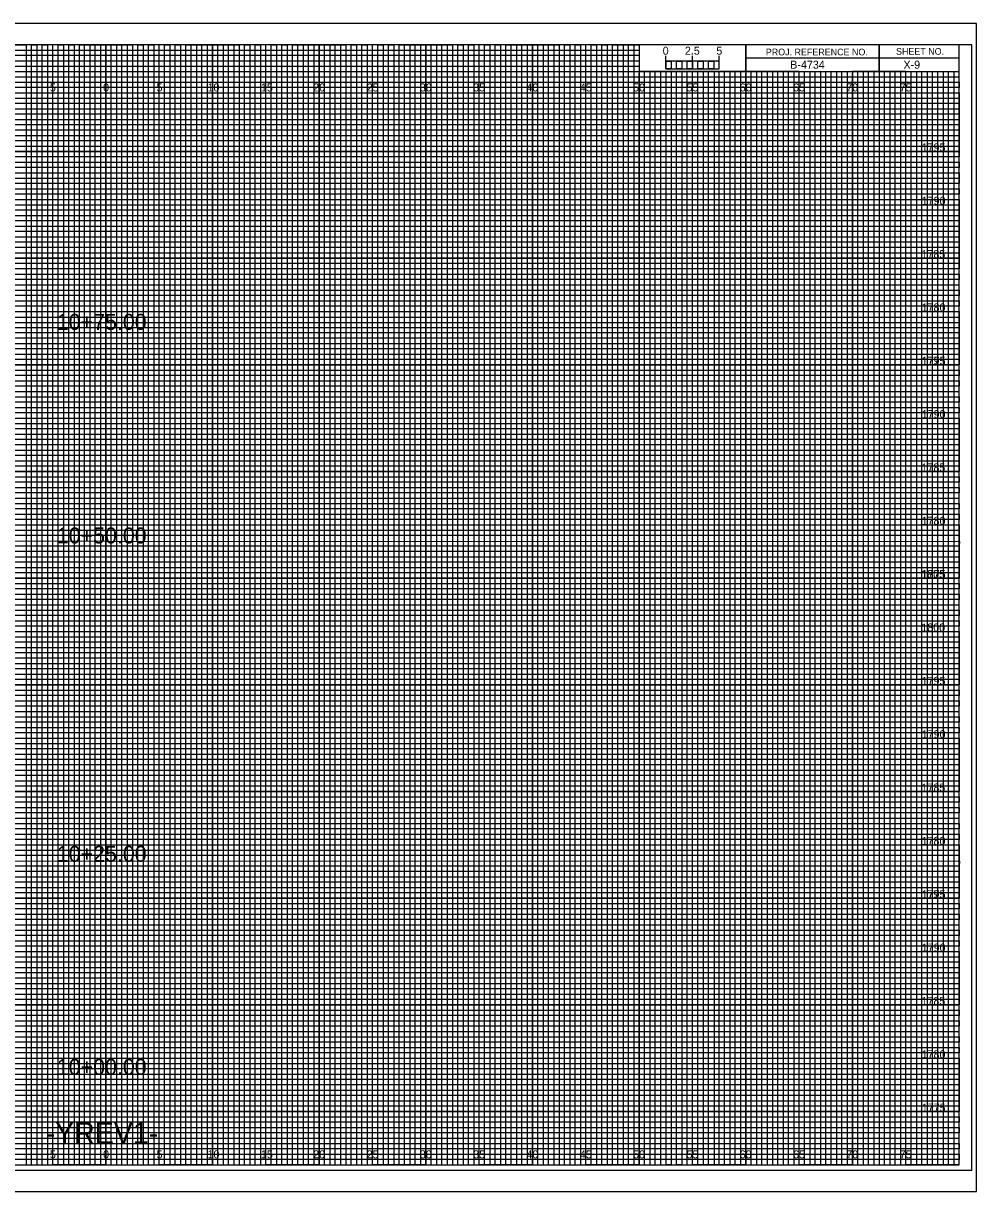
# Model space of a CAD drawing. Extents: x -7 to 162, y -2 to 107.
# Drawn here: x 72.2 to 161.7, y -2.5 to 107 of the extents above; entities that cross this region are included whole.
import ezdxf

# ---------------------------------------------------------------- set-up
doc = ezdxf.new("R2010")
doc.units = 0
for name, color, linetype in [('Exist Cross Section Cell', 7, 'Continuous'), ('Exist XS Center Line Elevation Label', 7, 'Continuous'), ('Exist XS Ground Line', 7, 'Continuous'), ('Prop XS Ditch Slope Text', 7, 'Continuous'), ('Prop XS Ditch Standard Text', 7, 'Continuous'), ('Prop XS Dump Level', 7, 'Continuous'), ('Prop XS Earthwork Shape', 7, 'Continuous'), ('Prop XS EOT Tick Mark', 7, 'Continuous'), ('Prop XS Finish Grade', 7, 'Continuous'), ('Prop XS Finish Grade Earthwork', 7, 'Continuous'), ('Prop XS Finish Grade Pavement', 7, 'Continuous'), ('Prop XS Pvmt Edge Slope', 7, 'Continuous'), ('Prop XS SE Text', 7, 'Continuous'), ('Prop XS Side Slope Text', 7, 'Continuous'), ('Prop XS SS Elevation Text', 7, 'Continuous'), ('Prop XS Subgrade Earthwork', 7, 'Continuous'), ('Scratch_Level_3', 7, 'Continuous')]:
    doc.layers.add(name, color=color, linetype=linetype)

msp = doc.modelspace()

# ---------------------------------------------------------------- linework, layer by layer
at = {"layer": 'Exist XS Center Line Elevation Label'}
for points in [[(67.5, 105), (72.5, 105), (72.5, 0), (77.5, 0), (77.5, 105), (82.5, 105), (82.5, 0), (87.5, 0), (87.5, 105), (92.5, 105), (92.5, 0), (97.5, 0), (97.5, 105), (102.5, 105), (102.5, 0), (107.5, 0), (107.5, 105), (112.5, 105), (112.5, 0), (117.5, 0), (117.5, 105), (122.5, 105), (122.5, 0), (127.5, 0), (127.5, 105), (129.97, 105), (130, 105), (130, 102.5), (132.5, 102.5), (132.5, 0), (137.5, 0), (137.5, 102.5), (142.5, 102.5), (142.5, 0), (147.5, 0), (147.5, 102.5), (152.5, 102.5), (152.5, 0), (157.5, 0), (157.5, 102.5)], [(0, 102.5), (137.5, 102.5)], [(0, 92.5), (160, 92.5), (160, 97.5), (0, 97.5)], [(0, 82.5), (160, 82.5), (160, 87.5), (0, 87.5)], [(0, 72.5), (160, 72.5), (160, 77.5), (0, 77.5)], [(0, 62.5), (160, 62.5), (160, 67.5), (0, 67.5)], [(0, 52.5), (160, 52.5), (160, 57.5), (0, 57.5)], [(0, 42.5), (160, 42.5), (160, 47.5), (0, 47.5)], [(0, 32.5), (160, 32.5), (160, 37.5), (0, 37.5)], [(0, 22.5), (160, 22.5), (160, 27.5), (0, 27.5)], [(0, 12.5), (160, 12.5), (160, 17.5), (0, 17.5)], [(0, 2.5), (160, 2.5), (160, 7.5), (0, 7.5)]]:
    msp.add_lwpolyline(points, dxfattribs=at)
at = {"layer": 'Exist XS Ground Line'}
for p, q in [((75, 105), (70, 105)), ((75, 0), (75, 105)), ((85, 105), (80, 105)), ((80, 105), (80, 0)), ((85, 0), (85, 105)), ((95, 105), (90, 105)), ((90, 105), (90, 0)), ((95, 0), (95, 105)), ((105, 105), (100, 105)), ((100, 105), (100, 0)), ((105, 0), (105, 105)), ((115, 105), (110, 105)), ((110, 105), (110, 0)), ((115, 0), (115, 105)), ((125, 105), (120, 105)), ((120, 105), (120, 0)), ((125, 0), (125, 105)), ((130, 105), (130, 0)), ((135, 0), (135, 102.5)), ((145, 102.5), (140, 102.5)), ((140, 102.5), (140, 0)), ((145, 0), (145, 102.5)), ((155, 102.5), (150, 102.5)), ((150, 102.5), (150, 0)), ((155, 0), (155, 102.5)), ((80, 0), (75, 0)), ((90, 0), (85, 0)), ((100, 0), (95, 0)), ((110, 0), (105, 0)), ((120, 0), (115, 0)), ((130, 0), (125, 0)), ((140, 0), (135, 0)), ((150, 0), (145, 0)), ((160, 0), (155, 0)), ((160, 0), (160, 0))]:
    msp.add_line(p, q, dxfattribs=at)
for points in [[(0, 100), (160, 100), (160, 95), (0, 95)], [(0, 90), (160, 90), (160, 85), (0, 85)], [(0, 80), (160, 80), (160, 75), (0, 75)], [(0, 70), (160, 70), (160, 65), (0, 65)], [(0, 60), (160, 60), (160, 55), (0, 55)], [(0, 50), (160, 50), (160, 45), (0, 45)], [(0, 40), (160, 40), (160, 35), (0, 35)], [(0, 30), (160, 30), (160, 25), (0, 25)], [(0, 20), (160, 20), (160, 15), (0, 15)], [(0, 10), (160, 10), (160, 5), (0, 5)]]:
    msp.add_lwpolyline(points, dxfattribs=at)
at = {"layer": 'Prop XS Ditch Slope Text'}
for p, q in [((132.5, 102.75), (132.5, 103.95)), ((132.5, 103.45), (132.5, 103.95)), ((135, 102.75), (135, 103.95)), ((137.5, 102.75), (137.5, 103.95)), ((137.5, 103.45), (137.5, 103.95))]:
    msp.add_line(p, q, dxfattribs=at)
for points in [[(137.5, 103.45), (132.5, 103.45), (132.5, 102.75), (137.5, 102.75)], [(132.5, 103.45), (133, 103.45), (133, 102.75), (132.5, 102.75)], [(133.5, 103.45), (134, 103.45), (134, 102.75), (133.5, 102.75)], [(134.5, 103.45), (135, 103.45), (135, 102.75), (134.5, 102.75)], [(135.5, 103.45), (136, 103.45), (136, 102.75), (135.5, 102.75)], [(136.5, 103.45), (137, 103.45), (137, 102.75), (136.5, 102.75)]]:
    msp.add_lwpolyline(points, close=True, dxfattribs=at)
at = {"layer": 'Prop XS Ditch Standard Text'}
for p, q in [((133.5, 102.5), (133, 102.5)), ((133, 102.5), (133, 0)), ((133.5, 0), (133.5, 102.5)), ((134.5, 102.5), (134, 102.5)), ((134, 102.5), (134, 0)), ((134.5, 0), (134.5, 102.5)), ((133, 0), (132.5, 0)), ((134, 0), (133.5, 0))]:
    msp.add_line(p, q, dxfattribs=at)
for points in [[(72.5, 0), (73, 0), (73, 105), (73.5, 105), (73.5, 0)], [(73.5, 0), (74, 0), (74, 105), (74.5, 105), (74.5, 0)], [(75, 0), (75.5, 0), (75.5, 105), (76, 105), (76, 0)], [(76, 0), (76.5, 0), (76.5, 105), (77, 105), (77, 0)], [(77.5, 0), (78, 0), (78, 105), (78.5, 105), (78.5, 0)], [(78.5, 0), (79, 0), (79, 105), (79.5, 105), (79.5, 0)], [(80, 0), (80.5, 0), (80.5, 105), (81, 105), (81, 0)], [(81, 0), (81.5, 0), (81.5, 105), (82, 105), (82, 0)], [(82.5, 0), (83, 0), (83, 105), (83.5, 105), (83.5, 0)], [(83.5, 0), (84, 0), (84, 105), (84.5, 105), (84.5, 0)], [(85, 0), (85.5, 0), (85.5, 105), (86, 105), (86, 0)], [(86, 0), (86.5, 0), (86.5, 105), (87, 105), (87, 0)], [(87.5, 0), (88, 0), (88, 105), (88.5, 105), (88.5, 0)], [(88.5, 0), (89, 0), (89, 105), (89.5, 105), (89.5, 0)], [(90, 0), (90.5, 0), (90.5, 105), (91, 105), (91, 0)], [(91, 0), (91.5, 0), (91.5, 105), (92, 105), (92, 0)], [(92.5, 0), (93, 0), (93, 105), (93.5, 105), (93.5, 0)], [(93.5, 0), (94, 0), (94, 105), (94.5, 105), (94.5, 0)], [(95, 0), (95.5, 0), (95.5, 105), (96, 105), (96, 0)], [(96, 0), (96.5, 0), (96.5, 105), (97, 105), (97, 0)], [(97.5, 0), (98, 0), (98, 105), (98.5, 105), (98.5, 0)], [(98.5, 0), (99, 0), (99, 105), (99.5, 105), (99.5, 0)], [(100, 0), (100.5, 0), (100.5, 105), (101, 105), (101, 0)], [(101, 0), (101.5, 0), (101.5, 105), (102, 105), (102, 0)], [(102.5, 0), (103, 0), (103, 105), (103.5, 105), (103.5, 0)], [(103.5, 0), (104, 0), (104, 105), (104.5, 105), (104.5, 0)], [(105, 0), (105.5, 0), (105.5, 105), (106, 105), (106, 0)], [(106, 0), (106.5, 0), (106.5, 105), (107, 105), (107, 0)], [(107.5, 0), (108, 0), (108, 105), (108.5, 105), (108.5, 0)], [(108.5, 0), (109, 0), (109, 105), (109.5, 105), (109.5, 0)], [(110, 0), (110.5, 0), (110.5, 105), (111, 105), (111, 0)], [(111, 0), (111.5, 0), (111.5, 105), (112, 105), (112, 0)], [(112.5, 0), (113, 0), (113, 105), (113.5, 105), (113.5, 0)], [(113.5, 0), (114, 0), (114, 105), (114.5, 105), (114.5, 0)], [(115, 0), (115.5, 0), (115.5, 105), (116, 105), (116, 0)], [(116, 0), (116.5, 0), (116.5, 105), (117, 105), (117, 0)], [(117.5, 0), (118, 0), (118, 105), (118.5, 105), (118.5, 0)], [(118.5, 0), (119, 0), (119, 105), (119.5, 105), (119.5, 0)], [(120, 0), (120.5, 0), (120.5, 105), (121, 105), (121, 0)], [(121, 0), (121.5, 0), (121.5, 105), (122, 105), (122, 0)], [(122.5, 0), (123, 0), (123, 105), (123.5, 105), (123.5, 0)], [(123.5, 0), (124, 0), (124, 105), (124.5, 105), (124.5, 0)], [(125, 0), (125.5, 0), (125.5, 105), (126, 105), (126, 0)], [(126, 0), (126.5, 0), (126.5, 105), (127, 105), (127, 0)], [(127.5, 0), (128, 0), (128, 105), (128.5, 105), (128.5, 0)], [(128.5, 0), (129, 0), (129, 105), (129.5, 105), (129.5, 0)], [(130, 0), (130.5, 0), (130.5, 102.5), (131.01, 102.5), (131.01, 0)], [(131, 0), (131.5, 0), (131.5, 102.5), (132, 102.5), (132, 0)], [(135, 0), (135.49, 0), (135.49, 102.5), (136, 102.5), (136, 0)], [(136, 0), (136.5, 0), (136.5, 102.5), (137.03, 102.5), (137.03, 0)], [(137.5, 0), (138, 0), (138, 102.5), (138.5, 102.5), (138.5, 0)], [(138.5, 0), (139, 0), (139, 102.5), (139.5, 102.5), (139.5, 0)], [(140, 0), (140.5, 0), (140.5, 102.5), (141, 102.5), (141, 0)], [(141, 0), (141.5, 0), (141.5, 102.5), (142, 102.5), (142, 0)], [(142.5, 0), (143, 0), (143, 102.5), (143.5, 102.5), (143.5, 0)], [(143.5, 0), (144, 0), (144, 102.5), (144.5, 102.5), (144.5, 0)], [(145, 0), (145.5, 0), (145.5, 102.5), (146, 102.5), (146, 0)], [(146, 0), (146.5, 0), (146.5, 102.5), (147, 102.5), (147, 0)], [(147.5, 0), (148, 0), (148, 102.5), (148.5, 102.5), (148.5, 0)], [(148.5, 0), (149, 0), (149, 102.5), (149.5, 102.5), (149.5, 0)], [(150, 0), (150.5, 0), (150.5, 102.5), (151, 102.5), (151, 0)], [(151, 0), (151.5, 0), (151.5, 102.5), (152, 102.5), (152, 0)], [(152.5, 0), (153, 0), (153, 102.5), (153.5, 102.5), (153.5, 0)], [(153.5, 0), (154, 0), (154, 102.5), (154.5, 102.5), (154.5, 0)], [(155, 0), (155.5, 0), (155.5, 102.5), (156, 102.5), (156, 0)], [(156, 0), (156.5, 0), (156.5, 102.5), (157, 102.5), (157, 0)], [(157.5, 0), (158, 0), (158, 102.5), (158.5, 102.5), (158.5, 0)], [(158.5, 0), (159, 0), (159, 102.5), (159.5, 102.5), (159.5, 0)]]:
    msp.add_lwpolyline(points, dxfattribs=at)
at = {"layer": 'Prop XS Dump Level'}
for p, q in [((0, 104.5), (130, 104.5)), ((130, 104.5), (130, 103.99)), ((130, 103.99), (0, 103.99)), ((0, 103.5), (130, 103.5)), ((130, 102.95), (0, 102.95)), ((130, 103.5), (130, 102.95)), ((0, 102), (160, 102))]:
    msp.add_line(p, q, dxfattribs=at)
for points in [[(0, 101.5), (135, 101.5), (160, 101.5), (160, 101), (0, 101)], [(0, 100.5), (160, 100.5), (160, 99.5), (0, 99.5)], [(0, 99), (160, 99), (160, 98.5), (0, 98.49)], [(0, 98), (160, 98), (160, 97), (0, 97)], [(0, 96.5), (160, 96.5), (160, 96), (0, 96)], [(0, 95.5), (160, 95.5), (160, 94.5), (0, 94.5)], [(0, 94), (160, 94), (160, 93.5), (0, 93.5)], [(0, 93), (160, 93), (160, 92), (0, 92)], [(0, 91.5), (160, 91.5), (160, 91), (0, 91)], [(0, 90.5), (160, 90.5), (160, 89.5), (0, 89.5)], [(0, 89), (160, 89), (160, 88.5), (0, 88.5)], [(0, 88), (160, 88), (160, 86.98), (160, 86.5), (160, 86), (0, 86)], [(0, 87), (160, 87), (160, 86.5), (0, 86.5)], [(0, 85.5), (160, 85.5), (160, 84.5), (0, 84.52)], [(0, 84.52), (160, 84.5), (160, 84), (0, 84)], [(0, 83.5), (160, 83.5), (160, 83), (0, 83)], [(0, 82), (160, 82), (160, 81.5), (0, 81.5)], [(0, 81), (160, 81), (160, 80.5), (0, 80.5)], [(-0.04, 79.45), (160, 79.45), (160, 78.94), (-0.04, 78.94)], [(0, 78.5), (160, 78.5), (160, 78), (0, 78)], [(0, 77), (160, 77), (160, 76.5), (0, 76.5)], [(0, 76), (160, 76), (160, 75.5), (0, 75.5)], [(0, 74.5), (160, 74.5), (160, 74), (0, 74)], [(0, 73.5), (160, 73.5), (160, 73), (0, 73)], [(0, 72), (160, 72), (160, 71.5), (0, 71.5)], [(0, 71), (160, 71), (160, 70.5), (0, 70.5)], [(0, 69.5), (160, 69.5), (160, 68.99), (0, 69)], [(0, 68.5), (160, 68.5), (160, 68), (0, 68)], [(0, 67), (160, 67), (160, 66.5), (0, 66.5)], [(0, 66), (160, 66), (160, 65.5), (0, 65.5)], [(0, 64.5), (160, 64.5), (160, 64), (0, 64)], [(0, 63.5), (160, 63.5), (160, 63), (0, 63)], [(0, 62), (160, 62), (160, 61.5), (0, 61.5)], [(0, 61), (160, 61), (160, 60.5), (0, 60.5)], [(0, 59.5), (160, 59.5), (160, 59), (0, 59)], [(0, 58.5), (160.03, 58.45), (160, 58), (0, 58)], [(0, 57), (160, 57), (160, 56.5), (0, 56.5)], [(0, 56), (160, 56), (160, 55.5), (0, 55.5)], [(0, 54.5), (160, 54.5), (160, 54), (0, 54)], [(0, 53.5), (160, 53.5), (160, 53), (0, 53)], [(0, 52), (160, 52), (160, 51.5), (0, 51.5)], [(0, 51), (160, 51), (160, 50.5), (0, 50.5)], [(0, 49.5), (160, 49.5), (160, 49), (0, 49)], [(0, 48.5), (160, 48.5), (160, 48), (0, 48)], [(0, 47), (160, 47), (160, 46.5), (0, 46.5)], [(0, 46), (160, 46), (160, 45.5), (0, 45.5)], [(0, 44.5), (160, 44.5), (160, 44), (0, 44)], [(0, 43.5), (160, 43.5), (160, 43), (0, 43)], [(0, 42), (160, 42), (160, 41.5), (0, 41.5)], [(0, 41), (160, 41), (160, 40.5), (0, 40.5)], [(0, 39.5), (160, 39.5), (160, 38.99), (0, 39)], [(0, 38.5), (160, 38.5), (160, 38), (0, 38)], [(0, 37), (160, 37), (160, 36.5), (0, 36.5)], [(0, 36), (160, 36), (160, 35.5), (0, 35.5)], [(0, 34.5), (160, 34.5), (160, 34), (0, 34)], [(0, 33.5), (160, 33.5), (160, 33), (0, 33)], [(0, 32), (160, 32), (160, 31.5), (0, 31.5)], [(0, 31), (160, 31), (160, 30.5), (0, 30.5)], [(0, 29.5), (160, 29.5), (160, 29), (0, 29)], [(0, 28.5), (160.03, 28.46), (160, 28), (0, 28)], [(0, 27), (160, 27), (160, 26.5), (0, 26.5)], [(0, 26), (160, 26), (160, 25.5), (0, 25.5)], [(0, 24.5), (160, 24.5), (160, 24), (0, 24)], [(0, 23.5), (160, 23.5), (160, 23), (0, 23)], [(0, 22), (160, 22), (160, 21.5), (0, 21.5)], [(0, 21), (160, 21), (160, 20.5), (0, 20.5)], [(0, 19.5), (160, 19.5), (160, 19), (0, 19)], [(0, 18.5), (160, 18.5), (160, 18), (0, 18)], [(0, 17), (160, 17), (160, 16.5), (0, 16.5)], [(0, 16), (160, 16), (160, 15.5), (0, 15.5)], [(0, 14.5), (160, 14.5), (160, 14), (0, 14)], [(0, 13.5), (160, 13.5), (160, 13), (0, 13)], [(0, 12), (160, 12), (160, 11.5), (0, 11.5)], [(0, 11), (160, 11), (160, 10.5), (0, 10.5)], [(0, 9.5), (160, 9.5), (160, 9), (0, 9)], [(0, 8.5), (160, 8.5), (160, 8), (0, 8)], [(0, 7), (160, 7), (160, 6.5), (0, 6.5)], [(0, 6), (160, 6), (160, 5.5), (0, 5.5)], [(0, 4.5), (160, 4.5), (160, 4), (0, 4)], [(0, 3.5), (160, 3.5), (160, 3), (0, 3)], [(0, 2), (160, 2), (160, 1.5), (0, 1.5)], [(0, 1), (160, 1), (160, 0.5), (0, 0.5)]]:
    msp.add_lwpolyline(points, dxfattribs=at)
at = {"layer": 'Prop XS Finish Grade Earthwork'}
for p, q in [((75, 0), (75, 105)), ((80, 0), (80, 105)), ((85, 0), (85, 105)), ((90, 0), (90, 105)), ((95, 0), (95, 105)), ((100, 0), (100, 105)), ((105, 0), (105, 105)), ((110, 0), (110, 105)), ((115, 0), (115, 105)), ((120, 0), (120, 105)), ((125, 0), (125, 105)), ((130, 0), (130, 102.34)), ((135, 0), (135, 102.34)), ((140, 0), (140, 102.34)), ((145, 0), (145, 102.34)), ((150, 0), (150, 102.34)), ((155, 0), (155, 102.34)), ((0, 100), (160, 100)), ((0, 95), (160, 95)), ((0, 90), (160, 90)), ((0, 85), (160, 85)), ((0, 80), (160, 80)), ((0, 75), (160, 75)), ((0, 70), (160, 70)), ((0, 65), (160, 65)), ((0, 60), (160, 60)), ((0, 55), (160, 55)), ((0, 50), (160, 50)), ((0, 45), (160, 45)), ((0, 40), (160, 40)), ((0, 35), (160, 35)), ((0, 30), (160, 30)), ((0, 25), (160, 25)), ((0, 20), (160, 20)), ((0, 15), (160, 15)), ((0, 10), (160, 10)), ((0, 5), (160, 5))]:
    msp.add_line(p, q, dxfattribs=at)
at = {"layer": 'Prop XS SE Text'}
for p, q in [((152.5, 105), (152.5, 102.5)), ((152.5, 102.5), (152.5, 105)), ((160, 103.75), (140, 103.75)), ((140, 103.75), (140, 102.5)), ((140, 102.5), (160, 102.5))]:
    msp.add_line(p, q, dxfattribs=at)
for points in [[(160, 105), (0, 105), (0, 0), (160, 0)], [(140, 105), (130, 105), (130, 102.52), (140, 102.52)], [(160, 105), (140, 105), (140, 102.5), (160, 102.5)]]:
    msp.add_lwpolyline(points, close=True, dxfattribs=at)
at = {"layer": 'Prop XS Side Slope Text'}
msp.add_lwpolyline([(-6.7, -2.5), (161.65, -2.5), (161.65, 107), (-6.7, 107)], close=True, dxfattribs=at)
at = {"layer": 'Prop XS SS Elevation Text'}
msp.add_lwpolyline([(-5.4, -0.5), (161.2, -0.5), (161.2, 105), (-5.4, 105)], close=True, dxfattribs=at)
at = {"layer": 'Prop XS Subgrade Earthwork'}
for p, q in [((161.65, 107), (-6.7, 107)), ((-6.7, -2.5), (161.65, -2.5))]:
    msp.add_line(p, q, dxfattribs=at)

# ---------------------------------------------------------------- texts
at = {"layer": 'Exist Cross Section Cell'}
for s, p in [('5', (74.74, 100.62)), ('0', (79.73, 100.62)), ('0', (79.73, 100.62)), ('5', (84.74, 100.62)), ('10', (89.52, 100.62)), ('15', (94.53, 100.62)), ('20', (99.43, 100.62)), ('25', (104.44, 100.62)), ('30', (109.43, 100.62)), ('35', (114.44, 100.62)), ('40', (119.43, 100.62)), ('45', (124.44, 100.62)), ('50', (129.43, 100.62)), ('55', (134.44, 100.62)), ('60', (139.43, 100.62)), ('65', (144.44, 100.62)), ('70', (149.43, 100.62)), ('75', (154.44, 100.62)), ('5', (74.74, 0.62)), ('0', (79.73, 0.62)), ('0', (79.73, 0.62)), ('5', (84.74, 0.62)), ('10', (89.52, 0.62)), ('15', (94.53, 0.62)), ('20', (99.43, 0.62)), ('25', (104.44, 0.62)), ('30', (109.43, 0.62)), ('35', (114.44, 0.62)), ('40', (119.43, 0.62)), ('45', (124.44, 0.62)), ('50', (129.43, 0.62)), ('55', (134.44, 0.62)), ('60', (139.43, 0.62)), ('65', (144.44, 0.62)), ('70', (149.43, 0.62)), ('75', (154.44, 0.62))]:
    msp.add_text(s, height=0.75, dxfattribs=at).set_placement(p)
at = {"layer": 'Prop XS Ditch Slope Text'}
msp.add_text('0', height=0.75, dxfattribs=at).set_placement((132.21, 104.06))
at = {"layer": 'Prop XS Earthwork Shape'}
for s, p in [('2.5', (134.29, 104.06)), ('5', (137.24, 104.06))]:
    msp.add_text(s, height=0.75, dxfattribs=at).set_placement(p)
at = {"layer": 'Prop XS EOT Tick Mark'}
msp.add_text('X-9', height=0.75, dxfattribs=at).set_placement((154.79, 102.75))
at = {"layer": 'Prop XS Finish Grade'}
for s, p in [('1795', (156.49, 95)), ('1790', (156.5, 90)), ('1785', (156.48, 85)), ('1780', (156.49, 80)), ('1795', (156.49, 75)), ('1775', (156.51, 75)), ('1790', (156.5, 70)), ('1785', (156.48, 65)), ('1780', (156.49, 60)), ('1805', (156.45, 55)), ('1775', (156.51, 55)), ('1800', (156.46, 50)), ('1795', (156.49, 45)), ('1790', (156.5, 40)), ('1785', (156.48, 35)), ('1780', (156.49, 30)), ('1795', (156.49, 25)), ('1775', (156.51, 25)), ('1790', (156.5, 20)), ('1785', (156.48, 15)), ('1780', (156.49, 10)), ('1775', (156.51, 5))]:
    msp.add_text(s, height=0.75, dxfattribs=at).set_placement(p)
at = {"layer": 'Prop XS Finish Grade Pavement'}
msp.add_text('B-4734', height=0.75, dxfattribs=at).set_placement((144.17, 102.75))
at = {"layer": 'Prop XS Pvmt Edge Slope'}
for s, p in [('10+75.00', (75.39, 78.27)), ('10+50.00', (75.39, 58.25)), ('10+25.00', (75.39, 28.41)), ('10+00.00', (75.39, 8.44))]:
    msp.add_text(s, height=1.5, dxfattribs=at).set_placement(p)
at = {"layer": 'Prop XS SE Text'}
for s, p in [('PROJ. REFERENCE NO.', (141.88, 104)), ('SHEET NO.', (154.09, 104.06))]:
    msp.add_text(s, height=0.625, dxfattribs=at).set_placement(p)
at = {"layer": 'Scratch_Level_3'}
msp.add_text('-YREV1-', height=2, dxfattribs=at).set_placement((74.34, 2))

doc.saveas('drawing.dxf')
